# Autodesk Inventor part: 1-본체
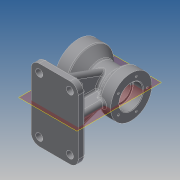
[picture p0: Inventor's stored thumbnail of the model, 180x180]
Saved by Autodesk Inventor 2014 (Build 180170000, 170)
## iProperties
Created: 2015-08
Part Number: 1-본체
Material: Aluminum 6061
Document SubType Name: Modeling
Designer: user
Density: 2.71 g/cm^3
Appearance: Default
Mass: 1055.88 g
Surface Area: 744.791 cm^2
Volume: 389.624 cm^3
Author: user
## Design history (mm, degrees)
sketch "Sketch1"
  geometry: L1 (-45, 0)-(45, 0); L2 (-45, 0)-(-45, 35); L3 (-45, 35)-(-25, 35); L4 (-25, 35)-(-19.804, 26); L5 (-19.804, 26)-(8.315, 26); L6 (8.315, 26)-(25, 40); L7 (25, 40)-(45, 40); L8 (45, 40)-(45, 0); 2 further points
  constraints: 16 end point, 2 horizontal, 1 coincident, 1 midpoint, 1 vertical
  dimensions: "d0" = 90 distance of L1.start L1.end; "d1" = 80 diameter of L7 L1; "d2" = 20 distance of L6.end L7.end; "d3" = 70 diameter of L3 L1; "d4" = 20 distance of L2.end L3.end; "d5" = 120 deg angle of L5 L4; "d6" = 140 deg angle of L6 L5; "d7" = 52 diameter of L5 L1
revolve "Revolution1" sketch "Sketch1" stored, may be unused: angle "d8" = 90 deg
workplane "Work Plane1"
sketch "Sketch2"
  geometry: L1 (-45, -61)-(-45, 61); L2 (-45, -35)-(-45, 35) reference; L3 (-45, 61)-(35, 61); L4 (35, 61)-(35, -61); L5 (35, -61)-(-45, -61); 1 further point
  constraints: 8 end point, 2 midpoint, 1 vertical
  dimensions: "d10" = 122 distance of L1.start L1.end
extrude "Extrusion1" join sketch "Sketch2" distance "d12" = 12; taper "d13" = 0 deg
sketch "Sketch3"
  geometry: L1 (35, -6)-(-25, -6); L2 (-25, -6)-(-25, 6); L3 (-25, 6)-(35, 6); L4 (35, 6)-(35, -6); L5 (35, -6)-(-25, 6); L6 (-25, -6)-(35, 6); 2 further points
  constraints: 12 end point, 2 midpoint
extrude "Extrusion2" join sketch "Sketch3" distance "d14" = 60; taper "d15" = 0 deg
workplane "Work Plane2"
workplane "Work Plane3"
sketch "Sketch10"
  geometry: L1 (70, 50)-(90, 50) reference; L2 (0, 12)-(80, 12) reference; L3 (70, 12)-(76.7, 50); 1 further point
  constraints: 2 end point, 2 point on line
  dimensions: "d112" = 80 deg angle of L2 L3; "d113" = 10 distance of L2.end L3.start
feature "Rib1" sketch "Sketch10" dims "d114" = 1, "d115" = 12, "d116" = 0, "d117" = 0, "d118" = 1, "d119" = 1
sketch "Sketch4"
  geometry: L1 (122, 0)-(0, 0) reference; L2 (0, 0)-(0, 12) reference; L3 (122, 12)-(0, 12) reference; L4 (122, 0)-(122, 12) reference; L5 (10, 12)-(35.909, 83.185); L6 (86.091, 83.185)-(112, 12); L7 (10, 12)-(112, 12); A1 r 26 centre (61, 90) between (67, 64.702) and (55, 64.702) reference; A2 r 26 centre (61, 90) between (35.909, 83.185) and (86.091, 83.185); 1 further point
  constraints: 6 end point, 4 point on circle, 2 point on line, 1 centre point, 1 coincident
  dimensions: "d16" = 70 deg angle of L3 L5; "d17" = 70 deg angle of L3 L6; "d18" = 10 distance of L3.start L6.end; "d19" = 10 distance from line of L5.start L2
extrude "Extrusion3" join sketch "Sketch4" stored distance "d20" = 12; taper "d21" = 0 deg
sketch "Sketch5"
  geometry: L1 (45, -61)-(45, 61) reference; L2 (-35, -61)-(45, -61) reference; 5 further points
  constraints: 2 horizontal alignment, 2 vertical alignment
  dimensions: "d22" = 94 distance of point (-21, -47) point (-21, 47); "d23" = 52 distance of point (31, -47) point (-21, -47); "d24" = 14 distance from line of L1 point (31, -47); "d25" = 14 distance from line of L2 point (-21, -47)
hole "Hole1" sketch "Sketch5" at (-21, 47), (31, 47), (31, -47), (-21, -47) diameter "d26" = 12; stored, may be unused: countersink angle "d30" = 90 deg, drill point angle "d32" = 118 deg; dims "d27" = 6, "d28" = 4, "d29" = 2, "d31" = 8
fillet "Fillet1" dims "d33" = 14, "d34" = 6
fillet "Fillet2" dims "d35" = 3
fillet "Fillet3" dims "d36" = 5
hole "Hole2" diameter "d39" = 40; stored, may be unused: countersink angle "d43" = 90 deg, drill point angle "d45" = 0 deg; dims "d37" = 10, "d38" = 10, "d40" = 6, "d41" = 4, "d42" = 2, "d44" = 17
hole "Hole3" diameter "d48" = 52; stored, may be unused: countersink angle "d52" = 90 deg, drill point angle "d54" = 0 deg; dims "d46" = 10, "d47" = 10, "d49" = 6, "d50" = 4, "d51" = 2, "d53" = 20
hole "Hole4" diameter "d57" = 38; stored, may be unused: countersink angle "d61" = 90 deg, drill point angle "d63" = 0 deg; dims "d55" = 10, "d56" = 10, "d58" = 6, "d59" = 4, "d60" = 2, "d62" = 3
hole "Hole5" diameter "d66" = 32; stored, may be unused: countersink angle "d70" = 90 deg, drill point angle "d72" = 0 deg; dims "d64" = 10, "d65" = 10, "d67" = 6, "d68" = 4, "d69" = 2, "d71" = 3
sketch "Sketch6"
  geometry: C1 r 35 at (0, 0) reference; 2 further points
  constraints: 1 coincident, 1 vertical alignment, 2 other
hole "Hole6" sketch "Sketch6" at (0, 27) diameter "d73" = 3.242; stored, may be unused: countersink angle "d77" = 90 deg, drill point angle "d79" = 118 deg; dims "d74" = 10, "d75" = 4, "d76" = 2, "d78" = 13
pattern_circular "Circular Pattern1" dims angle "d81" = 360 deg
sketch "Sketch7"
  geometry: C1 r 40 at (0, 0) reference; 2 further points
  constraints: 1 coincident, 1 vertical alignment, 2 other
hole "Hole7" sketch "Sketch7" at (0, 33) diameter "d83" = 3.242; stored, may be unused: countersink angle "d87" = 90 deg, drill point angle "d89" = 118 deg; dims "d84" = 10, "d85" = 4, "d86" = 2, "d88" = 13
pattern_circular "Circular Pattern2" dims angle "d91" = 360 deg
fillet "Fillet4" dims "d93" = 0.3, "d94" = 3
chamfer "Chamfer1" distance "d95" = 1; stored, may be unused: second distance "d96" = 2, angle "d97" = 45 deg
sketch "Sketch8"
  geometry: L1 (-13, -3)-(-2, -3) reference; L2 (-6, 0)-(-6, 37) reference; 2 further points
  constraints: 1 other
  dimensions: "d98" = 24 distance from line of L1 point (10, 21); "d99" = 16 distance from line of L2 point (10, 21)
emboss "Emboss1" sketch "Sketch8" dims "d0" = 90, "d1" = 80, "d2" = 20, "d3" = 70, "d4" = 20, "d5" = 120 deg, "d6" = 140 deg, "d7" = 52, "d100" = 0.5, "d101" = 0
sketch "Sketch9"
  geometry: L1 (-85, 30)-(-85, 36); L2 (-79, 30)-(-79, 36); L3 (-91, 36)-(-91, 30); L4 (-14, 12)-(-108, 12) reference; L5 (-37, 30)-(-37, 36); L6 (-31, 30)-(-31, 36); L7 (-43, 36)-(-43, 30); L8 (-85, 33)-(-37, 33); A1 r 6 centre (-85, 30) between (-91, 30) and (-79, 30); A2 r 6 centre (-85, 36) between (-79, 36) and (-91, 36); A3 r 6 centre (-37, 30) between (-43, 30) and (-31, 30); A4 r 6 centre (-37, 36) between (-31, 36) and (-43, 36); 2 further points
  constraints: 18 end point, 8 point on circle, 8 tangent, 4 centre point, 4 midpoint, 2 parallel, 1 horizontal alignment, 1 vertical alignment
  dimensions: "d102" = 12 distance between parallel lines of L2 L3; "d103" = 18 dimension on A2 A1; "d105" = 18 dimension on A3 A4; "d106" = 12 distance between parallel lines of L7 L6; "d107" = 18 distance from line of L4 L1.start; "d108" = 48 distance of L8.start L8.end; "d109" = 18 distance from line of L4 L5.start
extrude "Extrusion4" cut sketch "Sketch9" stored distance "d110" = 60; taper "d111" = 0 deg
fillet "Fillet5" dims "d120" = 6
fillet "Fillet6" dims "d121" = 3
body "Solid1"
node "Projected Loop1"
